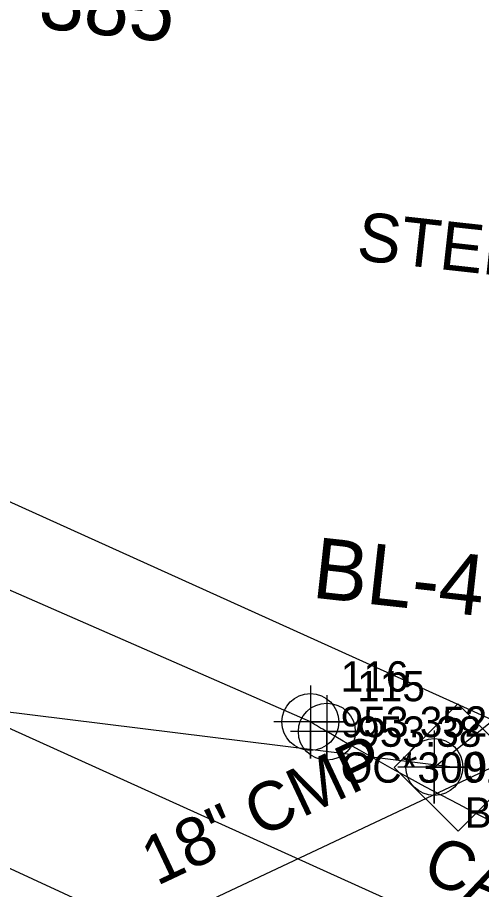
# Model space of a CAD drawing. Extents: x 1150279 to 1151282, y 655434 to 657999.
# Drawn here: x 1150895 to 1150933.3, y 657096 to 657167.8 of the extents above; entities that cross this region are included whole.
import ezdxf

# ---------------------------------------------------------------- set-up
doc = ezdxf.new("R2010")
doc.units = 0
for name, color, linetype in [('COGO Default Chain', 7, 'Continuous'), ('CTL Supplemental Horizontal and Vertical CELL', 7, 'Continuous'), ('CTL Supplemental Horizontal and Vertical Text', 7, 'Continuous'), ('Exist Building Text', 7, 'Continuous'), ('Exist Horizontal Alignment', 7, 'Continuous'), ('Exist Property Deed Book Text', 7, 'Continuous'), ('Exist Right of Way Line', 7, 'Continuous'), ('Exist Roads EOP', 7, 'Continuous'), ('Exist Roads EOP Cogo Comment', 7, 'Continuous'), ('Exist Roads EOP Cogo Elevation', 7, 'Continuous'), ('Exist Roads EOP Cogo Number', 7, 'Continuous'), ('Exist Roads EOP Cogo Point CELL', 7, 'Continuous'), ('Exist Roads EOP Text', 7, 'Continuous'), ('Exist Structure Minor Pipes CMP 18 Inch', 7, 'Continuous'), ('Exist Structure Minor Pipes CMP 18 Inch Text', 7, 'Continuous')]:
    doc.layers.add(name, color=color, linetype=linetype)

msp = doc.modelspace()

# ---------------------------------------------------------------- linework, layer by layer
at = {"layer": 'COGO Default Chain'}
for p, q in [((1150614.756, 657145.261), (1150931.292, 657106.062)), ((1150875.785, 657117.706), (1150962.476, 657078.528))]:
    msp.add_line(p, q, dxfattribs=at)
at = {"layer": 'CTL Supplemental Horizontal and Vertical CELL'}
msp.add_line((1150931.292, 657106.062), (1150931.292, 657106.062), dxfattribs=at)
msp.add_lwpolyline([(1150926.077, 657106.08), (1150931.318, 657111.321), (1150936.569, 657106.071), (1150931.327, 657100.83)], close=True, dxfattribs=at)
at = {"layer": 'Exist Horizontal Alignment'}
msp.add_line((1150875.785, 657117.706), (1150962.476, 657078.528), dxfattribs=at)
at = {"layer": 'Exist Right of Way Line'}
msp.add_line((1150882.786, 657133.198), (1150944.003, 657105.532), dxfattribs=at)
at = {"layer": 'Exist Roads EOP'}
for p, q in [((1150919.164, 657109.821), (1150874.311, 657129.486)), ((1150910.091, 657090.545), (1150866.518, 657110.593))]:
    msp.add_line(p, q, dxfattribs=at)
msp.add_lwpolyline([(1150929.365, 657106.111), (1150938.865, 657113.677), (1150959.994, 657129.491)], dxfattribs=at)
msp.add_spline([(1151056.232, 657077.091), (1151010.245, 657076.049), (1150965.316, 657087.792), (1150920.52, 657109.03), (1150919.164, 657109.821)], degree=3, dxfattribs=at)
at = {"layer": 'Exist Roads EOP Cogo Point CELL'}
for points in [[(1150919.164, 657112.821), (1150919.164, 657106.821), (1150919.164, 657109.821), (1150922.164, 657109.821), (1150916.164, 657109.821)], [(1150920.52, 657112.03), (1150920.52, 657106.03), (1150920.52, 657109.03), (1150923.52, 657109.03), (1150917.52, 657109.03)], [(1150929.365, 657109.111), (1150929.365, 657103.111), (1150929.365, 657106.111), (1150932.365, 657106.111), (1150926.365, 657106.111)]]:
    msp.add_lwpolyline(points, dxfattribs=at)
for centre in [(1150919.164, 657109.821), (1150920.52, 657109.03), (1150929.365, 657106.111)]:
    msp.add_circle(centre, 2.344, dxfattribs=at)
at = {"layer": 'Exist Structure Minor Pipes CMP 18 Inch'}
msp.add_line((1150936.288, 657107.106), (1150895.921, 657088.095), dxfattribs=at)

# ---------------------------------------------------------------- texts
at = {"layer": 'CTL Supplemental Horizontal and Vertical Text'}
msp.add_text('BL-4', height=5, rotation=353.6867, dxfattribs=at).set_placement((1150919.205, 657120.078))
at = {"layer": 'Exist Building Text'}
msp.add_text('STEPS', height=4, rotation=353.6867, dxfattribs=at).set_placement((1150922.885, 657147.878))
at = {"layer": 'Exist Property Deed Book Text'}
msp.add_text('DB 836 PG 385', height=5, rotation=353.6867, dxfattribs=at).set_placement((1150861.2, 657170.919))
at = {"layer": 'Exist Roads EOP Cogo Comment'}
for s, p in [('OC*30013', (1150921.664, 657104.821)), ('BL*30018', (1150931.865, 657101.111))]:
    msp.add_text(s, height=2.5, dxfattribs=at).set_placement(p)
at = {"layer": 'Exist Roads EOP Cogo Elevation'}
for s, p in [('953.35', (1150921.664, 657108.571)), ('953.38', (1150923.02, 657107.78)), ('953.45', (1150931.865, 657104.861))]:
    msp.add_text(s, height=2.5, dxfattribs=at).set_placement(p)
at = {"layer": 'Exist Roads EOP Cogo Number'}
for s, p in [('116', (1150921.664, 657112.321)), ('115', (1150923.02, 657111.53)), ('260', (1150931.865, 657108.611))]:
    msp.add_text(s, height=2.5, dxfattribs=at).set_placement(p)
at = {"layer": 'Exist Roads EOP Text'}
msp.add_text('CANE CREEK MTN. RD.', height=4, rotation=337.10646, dxfattribs=at).set_placement((1150928.179, 657096.94))
at = {"layer": 'Exist Structure Minor Pipes CMP 18 Inch Text'}
msp.add_text('18" CMP', height=4, rotation=25.21932, dxfattribs=at).set_placement((1150906.519, 657096.292))

doc.saveas('drawing.dxf')
